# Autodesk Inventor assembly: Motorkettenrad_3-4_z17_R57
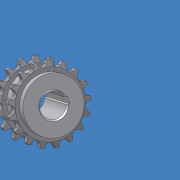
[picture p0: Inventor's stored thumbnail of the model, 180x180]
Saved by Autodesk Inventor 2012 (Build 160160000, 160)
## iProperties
Company: CAD-Verlag
Created: 2004-09
Part Number: Motorkettenrad_3-4_z17_R57
Document SubType Name: Assembly
Designer: Greiling
Manufacturer: Standard
Standards Organization: Custom
Control State: 0
Master: False
Checked Out: False
Shininess: 64.0
Length Units: 11269
Angle Units: 11279
Time Units: 11290
Mass Units: 11283
Length Display Precision: 3
Angle Display Precision: 2
Compacted: True
Density: 0.0
Volumn: 0.0
Area: 0.0
PropertySet Name: Model Information
Author: Jürgen Kronas
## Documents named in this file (3)
- C:\DemoDaten2012\CAD Daten\Daten Vault 2012 Inventor\Kapitel 6\6.4\Rollenbahn\Rollenbahn 1400\Motorkettenrad_3-4_z17_R57.iam
- C:\DemoDaten2012\CAD Daten\Daten Vault 2012 Inventor\Kapitel 6\6.4\Rollenbahn\Rollenbahn 1400\Kettenrad_kern.ipt
- C:\DemoDaten2012\CAD Daten\Daten Vault 2012 Inventor\Kapitel 6\6.4\Rollenbahn\Rollenbahn 1400\3_4_z17.iam
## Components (3 placed, 2 different names)
1. Kettenrad_kern:1 — Fluchtend:1, Fluchtend:2, Passend:1
2. 3_4_z17:1 [sub-assembly] — Fluchtend:2, Passend:1, Fluchtend:3
3. 3_4_z17:2 [sub-assembly] — Fluchtend:1, Fluchtend:3
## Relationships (4: Flush 3, Mate 1)
- Fluchtend:1 [Flush]: Kettenrad_kern:1 ↔ 3_4_z17:2
- Fluchtend:2 [Flush]: Kettenrad_kern:1 ↔ 3_4_z17:1
- Passend:1 [Mate]: Kettenrad_kern:1 ↔ 3_4_z17:1
- Fluchtend:3 [Flush]: 3_4_z17:1 ↔ 3_4_z17:2
